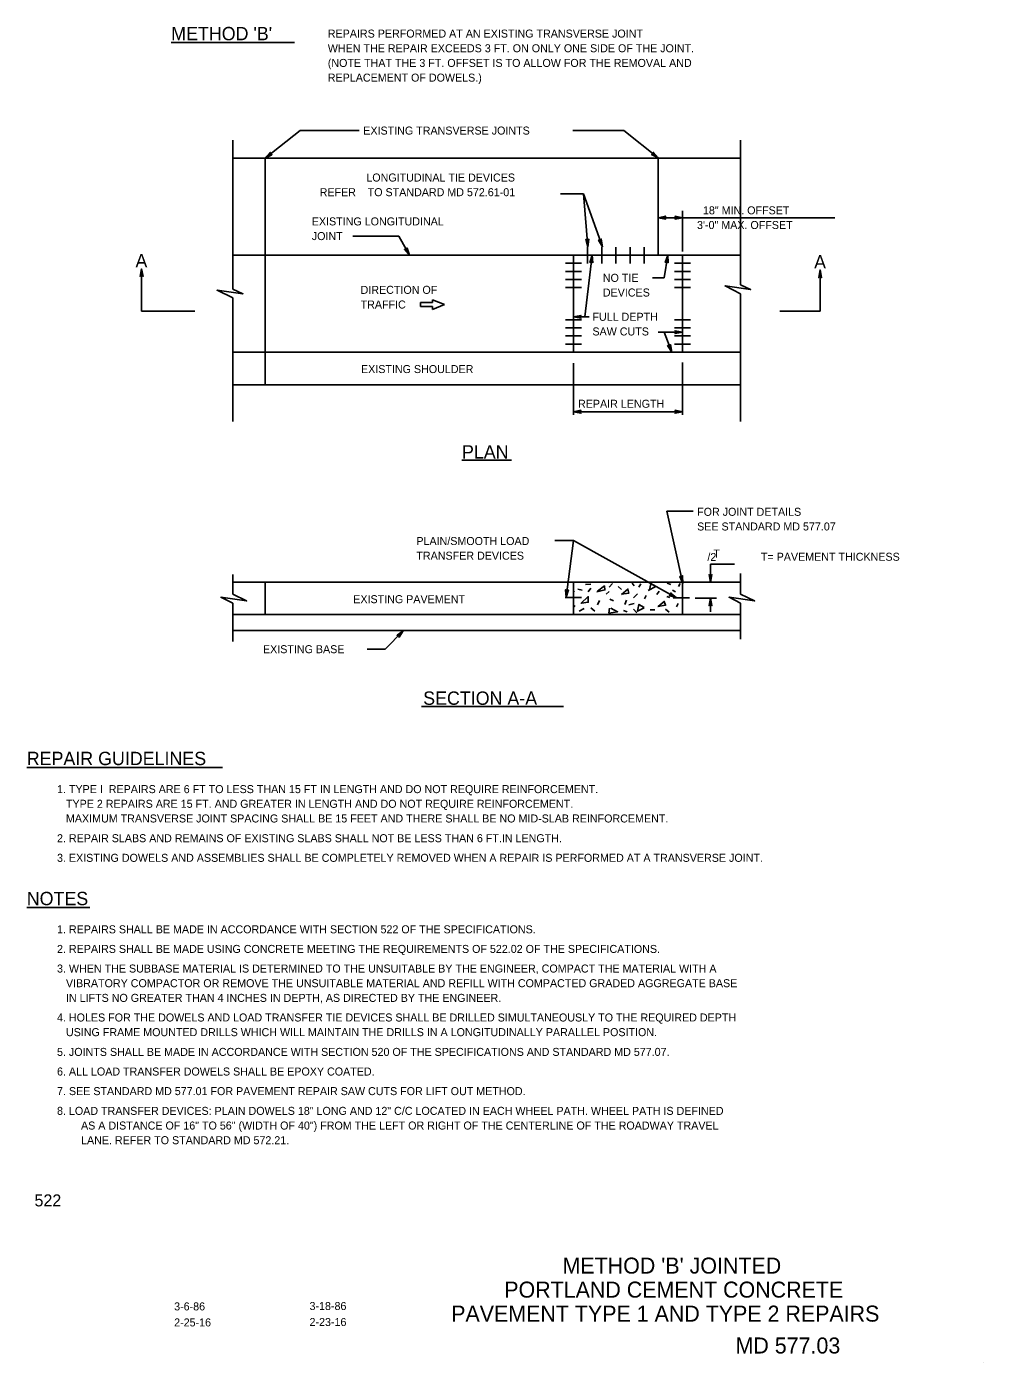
# Model space of a CAD drawing. Extents: x 1.1 to 8.2, y 0.2 to 10.2.
import ezdxf

# ---------------------------------------------------------------- set-up
doc = ezdxf.new("R2010")
doc.units = 0
for name, color, linetype in [('DETL-DIMS', 7, 'Continuous'), ('DETL-LINE', 7, 'Continuous'), ('DETL-NOTE', 7, 'Continuous'), ('DETL-PATT', 7, 'Continuous'), ('DETL-TITL', 7, 'Continuous'), ('TTLB-TEXT', 7, 'Continuous')]:
    doc.layers.add(name, color=color, linetype=linetype)

msp = doc.modelspace()

# ---------------------------------------------------------------- linework, layer by layer
at = {"layer": 'DETL-DIMS'}
for p, q in [((3.102, 9.42), (2.84, 9.212)), ((3.102, 9.42), (3.544, 9.42)), ((5.146, 9.42), (5.529, 9.42)), ((5.529, 9.42), (5.788, 9.215)), ((5.228, 8.945), (5.054, 8.945)), ((5.26, 8.549), (5.228, 8.945)), ((5.228, 8.945), (5.369, 8.549)), ((5.97, 8.513), (5.97, 8.819)), ((5.97, 8.767), (5.788, 8.767)), ((5.97, 8.767), (7.111, 8.767)), ((3.498, 8.629), (3.842, 8.629)), ((3.842, 8.629), (3.922, 8.485)), ((5.292, 8.486), (5.236, 8.024)), ((5.859, 8.486), (5.833, 8.316)), ((1.914, 8.066), (1.914, 8.383)), ((5.833, 8.316), (5.745, 8.316)), ((7.001, 8.066), (7.001, 8.375)), ((4.004, 8.1), (4.004, 8.132)), ((4.004, 8.132), (4.095, 8.132)), ((4.095, 8.132), (4.095, 8.152)), ((4.095, 8.152), (4.186, 8.116)), ((4.186, 8.116), (4.095, 8.079)), ((1.914, 8.066), (2.313, 8.066)), ((4.095, 8.1), (4.004, 8.1)), ((4.095, 8.079), (4.095, 8.1)), ((5.151, 8.024), (5.27, 8.024)), ((6.7, 8.066), (7.001, 8.066)), ((5.97, 7.908), (5.786, 7.908)), ((5.831, 7.908), (5.888, 7.759)), ((5.151, 7.29), (5.151, 7.676)), ((5.97, 7.29), (5.97, 7.681)), ((5.151, 7.312), (5.97, 7.312)), ((5.972, 6.025), (5.851, 6.567)), ((5.851, 6.567), (6.049, 6.567)), ((5.151, 6.347), (5.012, 6.347)), ((5.096, 5.921), (5.151, 6.347)), ((5.925, 5.917), (5.151, 6.347)), ((6.18, 6.169), (6.358, 6.169)), ((6.18, 6.035), (6.18, 6.169)), ((6.064, 5.915), (6.224, 5.915)), ((6.18, 5.813), (6.18, 5.915)), ((3.876, 5.67), (3.739, 5.532)), ((3.739, 5.532), (3.606, 5.532))]:
    msp.add_line(p, q, dxfattribs=at)
for points in [[(2.84, 9.212), (2.891, 9.239), (2.886, 9.239), (2.881, 9.24), (2.879, 9.243), (2.877, 9.246), (2.876, 9.251), (2.878, 9.256), (2.84, 9.212), (2.876, 9.251), (2.877, 9.246), (2.84, 9.212), (2.879, 9.243), (2.881, 9.24), (2.84, 9.212), (2.886, 9.239)], [(5.788, 9.215), (5.737, 9.241), (5.742, 9.241), (5.747, 9.243), (5.749, 9.245), (5.751, 9.249), (5.752, 9.253), (5.75, 9.258), (5.788, 9.215), (5.752, 9.253), (5.751, 9.249), (5.788, 9.215), (5.749, 9.245), (5.747, 9.243), (5.788, 9.215), (5.742, 9.241)], [(5.788, 8.767), (5.844, 8.778), (5.84, 8.775), (5.838, 8.771), (5.837, 8.767), (5.838, 8.763), (5.84, 8.76), (5.844, 8.756), (5.788, 8.767), (5.84, 8.76), (5.838, 8.763), (5.788, 8.767), (5.837, 8.767), (5.838, 8.771), (5.788, 8.767), (5.84, 8.775)], [(5.788, 8.767), (5.844, 8.778), (5.84, 8.775), (5.838, 8.771), (5.837, 8.767), (5.838, 8.763), (5.84, 8.76), (5.844, 8.756), (5.788, 8.767), (5.84, 8.76), (5.838, 8.763), (5.788, 8.767), (5.837, 8.767), (5.838, 8.771), (5.788, 8.767), (5.84, 8.775)], [(5.97, 8.767), (5.913, 8.756), (5.917, 8.76), (5.92, 8.763), (5.92, 8.767), (5.92, 8.771), (5.917, 8.775), (5.913, 8.778), (5.97, 8.767), (5.917, 8.775), (5.92, 8.771), (5.97, 8.767), (5.92, 8.767), (5.92, 8.763), (5.97, 8.767), (5.917, 8.76)], [(3.922, 8.485), (3.885, 8.529), (3.89, 8.527), (3.895, 8.527), (3.898, 8.528), (3.901, 8.53), (3.903, 8.534), (3.904, 8.539), (3.922, 8.485), (3.903, 8.534), (3.901, 8.53), (3.922, 8.485), (3.898, 8.528), (3.895, 8.527), (3.922, 8.485), (3.89, 8.527)], [(5.26, 8.549), (5.245, 8.605), (5.248, 8.6), (5.252, 8.598), (5.256, 8.598), (5.259, 8.599), (5.263, 8.602), (5.266, 8.606), (5.26, 8.549), (5.263, 8.602), (5.259, 8.599), (5.26, 8.549), (5.256, 8.598), (5.252, 8.598), (5.26, 8.549), (5.248, 8.6)], [(5.369, 8.549), (5.34, 8.599), (5.344, 8.596), (5.349, 8.595), (5.353, 8.595), (5.356, 8.597), (5.359, 8.601), (5.36, 8.606), (5.369, 8.549), (5.359, 8.601), (5.356, 8.597), (5.369, 8.549), (5.353, 8.595), (5.349, 8.595), (5.369, 8.549), (5.344, 8.596)], [(5.292, 8.486), (5.296, 8.429), (5.293, 8.434), (5.29, 8.436), (5.286, 8.438), (5.282, 8.437), (5.278, 8.436), (5.275, 8.432), (5.292, 8.486), (5.278, 8.436), (5.282, 8.437), (5.292, 8.486), (5.286, 8.438), (5.29, 8.436), (5.292, 8.486), (5.293, 8.434)], [(5.859, 8.486), (5.861, 8.429), (5.858, 8.434), (5.855, 8.437), (5.851, 8.438), (5.847, 8.438), (5.843, 8.436), (5.84, 8.432), (5.859, 8.486), (5.843, 8.436), (5.847, 8.438), (5.859, 8.486), (5.851, 8.438), (5.855, 8.437), (5.859, 8.486), (5.858, 8.434)], [(1.914, 8.383), (1.925, 8.327), (1.922, 8.331), (1.918, 8.333), (1.914, 8.334), (1.91, 8.333), (1.906, 8.331), (1.903, 8.327), (1.914, 8.383), (1.906, 8.331), (1.91, 8.333), (1.914, 8.383), (1.914, 8.334), (1.918, 8.333), (1.914, 8.383), (1.922, 8.331)], [(1.914, 8.383), (1.925, 8.327), (1.922, 8.331), (1.918, 8.333), (1.914, 8.334), (1.91, 8.333), (1.906, 8.331), (1.903, 8.327), (1.914, 8.383), (1.906, 8.331), (1.91, 8.333), (1.914, 8.383), (1.914, 8.334), (1.918, 8.333), (1.914, 8.383), (1.922, 8.331)], [(1.914, 8.383), (1.925, 8.327), (1.922, 8.331), (1.918, 8.333), (1.914, 8.334), (1.91, 8.333), (1.906, 8.331), (1.903, 8.327), (1.914, 8.383), (1.906, 8.331), (1.91, 8.333), (1.914, 8.383), (1.914, 8.334), (1.918, 8.333), (1.914, 8.383), (1.922, 8.331)], [(1.914, 8.383), (1.925, 8.327), (1.922, 8.331), (1.918, 8.333), (1.914, 8.334), (1.91, 8.333), (1.906, 8.331), (1.903, 8.327), (1.914, 8.383), (1.906, 8.331), (1.91, 8.333), (1.914, 8.383), (1.914, 8.334), (1.918, 8.333), (1.914, 8.383), (1.922, 8.331)], [(7.001, 8.375), (7.012, 8.318), (7.009, 8.323), (7.005, 8.325), (7.001, 8.326), (6.997, 8.325), (6.994, 8.323), (6.991, 8.318), (7.001, 8.375), (6.994, 8.323), (6.997, 8.325), (7.001, 8.375), (7.001, 8.326), (7.005, 8.325), (7.001, 8.375), (7.009, 8.323)], [(5.151, 8.024), (5.208, 8.034), (5.204, 8.031), (5.201, 8.028), (5.201, 8.024), (5.201, 8.02), (5.204, 8.016), (5.208, 8.013), (5.151, 8.024), (5.204, 8.016), (5.201, 8.02), (5.151, 8.024), (5.201, 8.024), (5.201, 8.028), (5.151, 8.024), (5.204, 8.031)], [(5.97, 7.908), (5.913, 7.898), (5.917, 7.901), (5.92, 7.904), (5.92, 7.908), (5.92, 7.912), (5.917, 7.916), (5.913, 7.919), (5.97, 7.908), (5.917, 7.916), (5.92, 7.912), (5.97, 7.908), (5.92, 7.908), (5.92, 7.904), (5.97, 7.908), (5.917, 7.901)], [(5.97, 7.908), (5.913, 7.898), (5.917, 7.901), (5.92, 7.904), (5.92, 7.908), (5.92, 7.912), (5.917, 7.916), (5.913, 7.919), (5.97, 7.908), (5.917, 7.916), (5.92, 7.912), (5.97, 7.908), (5.92, 7.908), (5.92, 7.904), (5.97, 7.908), (5.917, 7.901)], [(5.888, 7.759), (5.858, 7.808), (5.862, 7.805), (5.866, 7.804), (5.87, 7.805), (5.873, 7.807), (5.876, 7.81), (5.878, 7.815), (5.888, 7.759), (5.876, 7.81), (5.873, 7.807), (5.888, 7.759), (5.87, 7.805), (5.866, 7.804), (5.888, 7.759), (5.862, 7.805)], [(5.151, 7.312), (5.208, 7.323), (5.204, 7.32), (5.201, 7.316), (5.201, 7.312), (5.201, 7.308), (5.204, 7.304), (5.208, 7.301), (5.151, 7.312), (5.204, 7.304), (5.201, 7.308), (5.151, 7.312), (5.201, 7.312), (5.201, 7.316), (5.151, 7.312), (5.204, 7.32)], [(5.151, 7.312), (5.208, 7.323), (5.204, 7.32), (5.201, 7.316), (5.201, 7.312), (5.201, 7.308), (5.204, 7.304), (5.208, 7.301), (5.151, 7.312), (5.204, 7.304), (5.201, 7.308), (5.151, 7.312), (5.201, 7.312), (5.201, 7.316), (5.151, 7.312), (5.204, 7.32)], [(5.97, 7.312), (5.913, 7.301), (5.917, 7.304), (5.92, 7.308), (5.92, 7.312), (5.92, 7.316), (5.917, 7.32), (5.913, 7.323), (5.97, 7.312), (5.917, 7.32), (5.92, 7.316), (5.97, 7.312), (5.92, 7.312), (5.92, 7.308), (5.97, 7.312), (5.917, 7.304)], [(5.972, 6.025), (5.95, 6.078), (5.954, 6.074), (5.958, 6.073), (5.962, 6.073), (5.965, 6.075), (5.968, 6.078), (5.97, 6.083), (5.972, 6.025), (5.968, 6.078), (5.965, 6.075), (5.972, 6.025), (5.962, 6.073), (5.958, 6.073), (5.972, 6.025), (5.954, 6.074)], [(6.18, 6.035), (6.169, 6.091), (6.172, 6.087), (6.176, 6.085), (6.18, 6.084), (6.183, 6.085), (6.187, 6.087), (6.19, 6.091), (6.18, 6.035), (6.187, 6.087), (6.183, 6.085), (6.18, 6.035), (6.18, 6.084), (6.176, 6.085), (6.18, 6.035), (6.172, 6.087)], [(5.096, 5.921), (5.093, 5.978), (5.095, 5.974), (5.099, 5.971), (5.102, 5.97), (5.106, 5.97), (5.11, 5.972), (5.114, 5.976), (5.096, 5.921), (5.11, 5.972), (5.106, 5.97), (5.096, 5.921), (5.102, 5.97), (5.099, 5.971), (5.096, 5.921), (5.095, 5.974)], [(5.925, 5.917), (5.871, 5.935), (5.876, 5.936), (5.88, 5.938), (5.882, 5.941), (5.884, 5.944), (5.884, 5.949), (5.881, 5.954), (5.925, 5.917), (5.884, 5.949), (5.884, 5.944), (5.925, 5.917), (5.882, 5.941), (5.88, 5.938), (5.925, 5.917), (5.876, 5.936)], [(6.18, 5.915), (6.19, 5.859), (6.187, 5.863), (6.183, 5.866), (6.18, 5.866), (6.176, 5.866), (6.172, 5.863), (6.169, 5.859), (6.18, 5.915), (6.172, 5.863), (6.176, 5.866), (6.18, 5.915), (6.18, 5.866), (6.183, 5.866), (6.18, 5.915), (6.187, 5.863)], [(3.876, 5.67), (3.844, 5.622), (3.845, 5.627), (3.844, 5.632), (3.842, 5.635), (3.838, 5.637), (3.834, 5.638), (3.829, 5.637), (3.876, 5.67), (3.834, 5.638), (3.838, 5.637), (3.876, 5.67), (3.842, 5.635), (3.844, 5.632), (3.876, 5.67), (3.845, 5.627)]]:
    msp.add_lwpolyline(points, dxfattribs=at)
at = {"layer": 'DETL-LINE'}
for p, q in [((2.598, 9.349), (2.598, 8.232)), ((6.405, 9.349), (6.405, 8.264)), ((2.598, 9.212), (6.405, 9.212)), ((2.84, 9.212), (2.84, 7.515)), ((5.788, 8.485), (5.788, 9.212)), ((5.257, 8.424), (5.257, 8.546)), ((5.364, 8.424), (5.364, 8.546)), ((5.47, 8.424), (5.47, 8.546)), ((5.576, 8.424), (5.576, 8.546)), ((5.682, 8.424), (5.682, 8.546)), ((2.598, 8.485), (6.405, 8.485)), ((5.091, 8.425), (5.212, 8.425)), ((5.151, 7.758), (5.151, 8.486)), ((6.03, 8.425), (5.909, 8.425)), ((5.97, 7.758), (5.97, 8.486)), ((5.97, 7.758), (5.97, 8.486)), ((5.091, 8.364), (5.212, 8.364)), ((6.03, 8.364), (5.909, 8.364)), ((5.091, 8.304), (5.212, 8.304)), ((5.091, 8.243), (5.212, 8.243)), ((6.03, 8.304), (5.909, 8.304)), ((6.03, 8.243), (5.909, 8.243)), ((2.598, 8.166), (2.598, 7.239)), ((6.405, 8.197), (6.405, 7.239)), ((5.091, 8.001), (5.212, 8.001)), ((5.091, 7.94), (5.212, 7.94)), ((6.03, 8.001), (5.909, 8.001)), ((6.03, 7.94), (5.909, 7.94)), ((5.091, 7.88), (5.212, 7.88)), ((5.091, 7.819), (5.212, 7.819)), ((6.03, 7.88), (5.909, 7.88)), ((6.03, 7.819), (5.909, 7.819)), ((2.598, 7.758), (6.405, 7.758)), ((2.598, 7.515), (6.405, 7.515)), ((2.598, 6.093), (2.598, 5.944)), ((2.598, 6.035), (6.405, 6.035)), ((2.84, 6.035), (2.84, 5.793)), ((5.151, 6.035), (5.151, 5.793)), ((5.97, 6.035), (5.97, 5.793)), ((6.405, 6.099), (6.405, 5.945)), ((5.151, 5.919), (5.09, 5.919)), ((5.151, 5.919), (5.212, 5.919)), ((5.899, 5.917), (6.021, 5.917)), ((2.598, 5.877), (2.598, 5.589)), ((6.405, 5.878), (6.405, 5.606)), ((2.598, 5.793), (6.405, 5.793)), ((2.598, 5.671), (6.405, 5.671))]:
    msp.add_line(p, q, dxfattribs=at)
for points in [[(2.598, 8.166), (2.48, 8.223), (2.673, 8.197), (2.598, 8.232)], [(6.405, 8.197), (6.288, 8.255), (6.48, 8.228), (6.405, 8.264)], [(2.598, 5.877), (2.509, 5.921), (2.701, 5.894), (2.598, 5.944)], [(6.405, 5.878), (6.318, 5.921), (6.51, 5.894), (6.405, 5.945)]]:
    msp.add_lwpolyline(points, dxfattribs=at)
at = {"layer": 'DETL-NOTE'}
for p, q in [((2.136, 10.08), (3.06, 10.08)), ((1.053, 4.646), (2.521, 4.646)), ((1.053, 3.596), (1.527, 3.596))]:
    msp.add_line(p, q, dxfattribs=at)
at = {"layer": 'DETL-PATT'}
for p, q in [((5.242, 6.016), (5.281, 6.019)), ((5.419, 5.996), (5.445, 6.025)), ((5.592, 6.028), (5.608, 6.006)), ((5.627, 6.035), (5.627, 6.035)), ((5.656, 6.022), (5.643, 5.996)), ((5.855, 6.028), (5.881, 6.016)), ((5.939, 6.003), (5.952, 6.025)), ((5.159, 5.967), (5.156, 5.964)), ((5.185, 5.983), (5.217, 5.974)), ((5.262, 5.961), (5.281, 5.99)), ((5.396, 5.945), (5.419, 5.964)), ((5.486, 6.003), (5.512, 5.98)), ((5.631, 5.948), (5.602, 5.916)), ((5.698, 5.935), (5.685, 5.91)), ((5.778, 5.942), (5.794, 5.967)), ((5.852, 5.926), (5.875, 5.919)), ((5.894, 5.974), (5.916, 5.961)), ((5.156, 5.858), (5.165, 5.852)), ((5.233, 5.836), (5.194, 5.817)), ((5.281, 5.842), (5.313, 5.817)), ((5.332, 5.865), (5.348, 5.897)), ((5.425, 5.906), (5.451, 5.894)), ((5.528, 5.823), (5.554, 5.813)), ((5.55, 5.9), (5.538, 5.868)), ((5.608, 5.874), (5.566, 5.865)), ((5.602, 5.833), (5.627, 5.804)), ((5.727, 5.826), (5.762, 5.826)), ((5.842, 5.833), (5.868, 5.81)), ((5.923, 5.849), (5.936, 5.874))]:
    msp.add_line(p, q, dxfattribs=at)
for points in [[(5.416, 6.035), (5.416, 6.032), (5.435, 6.035)], [(5.711, 5.971), (5.769, 6.003), (5.733, 6.022), (5.721, 5.977)], [(5.213, 5.878), (5.262, 5.884), (5.262, 5.926), (5.207, 5.874)], [(5.326, 5.961), (5.387, 5.977), (5.384, 6.006), (5.332, 5.967)], [(5.512, 5.945), (5.566, 5.951), (5.56, 5.983), (5.512, 5.942)], [(5.422, 5.839), (5.416, 5.801)], [(5.416, 5.801), (5.483, 5.813), (5.432, 5.839)], [(5.682, 5.842), (5.631, 5.817), (5.643, 5.868), (5.682, 5.845)], [(5.785, 5.852), (5.842, 5.862), (5.833, 5.89), (5.788, 5.852)]]:
    msp.add_lwpolyline(points, dxfattribs=at)
at = {"layer": 'DETL-TITL'}
for p, q in [((4.316, 6.949), (4.686, 6.949)), ((4.012, 5.102), (5.077, 5.102))]:
    msp.add_line(p, q, dxfattribs=at)
at = {"layer": 'TTLB-TEXT'}
msp.add_line((8.224, 0.186), (8.224, 0.186), dxfattribs=at)

# ---------------------------------------------------------------- texts
at = {"layer": 'DETL-NOTE'}
for s, height, p in [("METHOD 'B'", 0.1, (2.136, 10.097)), ('REPAIRS PERFORMED AT AN EXISTING TRANSVERSE JOINT', 0.06, (3.31, 10.117)), ('WHEN THE REPAIR EXCEEDS 3 FT. ON ONLY ONE SIDE OF THE JOINT.', 0.06, (3.31, 10.007)), ('(NOTE THAT THE 3 FT. OFFSET IS TO ALLOW FOR THE REMOVAL AND', 0.06, (3.31, 9.897)), ('REPLACEMENT OF DOWELS.)', 0.06, (3.31, 9.787)), ('EXISTING TRANSVERSE JOINTS', 0.06, (3.576, 9.39)), ('LONGITUDINAL TIE DEVICES', 0.06, (3.599, 9.038)), ('REFER ', 0.06, (3.249, 8.928)), ('TO STANDARD MD 572.61-01', 0.06, (3.609, 8.928)), ('  18" MIN. OFFSET', 0.06, (6.078, 8.792)), ('EXISTING LONGITUDINAL', 0.06, (3.19, 8.709)), ('3\'-0" MAX. OFFSET', 0.06, (6.078, 8.682)), ('JOINT ', 0.06, (3.19, 8.599)), ('A', 0.1, (1.868, 8.394)), ('A', 0.1, (6.956, 8.386)), ('NO TIE', 0.06, (5.372, 8.286)), ('DIRECTION OF', 0.06, (3.556, 8.196)), ('DEVICES', 0.06, (5.372, 8.176)), ('TRAFFIC', 0.06, (3.556, 8.086)), ('FULL DEPTH', 0.06, (5.294, 7.994)), ('SAW CUTS', 0.06, (5.294, 7.884)), ('EXISTING SHOULDER', 0.06, (3.559, 7.602)), ('REPAIR LENGTH', 0.06, (5.186, 7.342)), ('FOR JOINT DETAILS', 0.06, (6.079, 6.532)), ('SEE STANDARD MD 577.07', 0.06, (6.079, 6.422)), ('PLAIN/SMOOTH LOAD ', 0.06, (3.974, 6.313)), ('TRANSFER DEVICES', 0.06, (3.974, 6.203)), ('  /2', 0.06, (6.111, 6.193)), ('T', 0.06, (6.2, 6.219)), ('T= PAVEMENT THICKNESS', 0.06, (6.557, 6.195)), ('EXISTING PAVEMENT', 0.06, (3.501, 5.877)), ('EXISTING BASE', 0.06, (2.824, 5.502)), ('REPAIR GUIDELINES', 0.1, (1.053, 4.663)), ('1. TYPE I  REPAIRS ARE 6 FT TO LESS THAN 15 FT IN LENGTH AND DO NOT REQUIRE REINFORCEMENT. ', 0.06, (1.28, 4.453)), ('   TYPE 2 REPAIRS ARE 15 FT. AND GREATER IN LENGTH AND DO NOT REQUIRE REINFORCEMENT. ', 0.06, (1.28, 4.343)), ('   MAXIMUM TRANSVERSE JOINT SPACING SHALL BE 15 FEET AND THERE SHALL BE NO MID-SLAB REINFORCEMENT.', 0.06, (1.28, 4.233)), ('2. REPAIR SLABS AND REMAINS OF EXISTING SLABS SHALL NOT BE LESS THAN 6 FT.IN LENGTH.', 0.06, (1.28, 4.085)), ('3. EXISTING DOWELS AND ASSEMBLIES SHALL BE COMPLETELY REMOVED WHEN A REPAIR IS PERFORMED AT A TRANSVERSE JOINT.', 0.06, (1.28, 3.938)), ('NOTES', 0.1, (1.053, 3.613)), ('1. REPAIRS SHALL BE MADE IN ACCORDANCE WITH SECTION 522 OF THE SPECIFICATIONS.', 0.06, (1.28, 3.402)), ('2. REPAIRS SHALL BE MADE USING CONCRETE MEETING THE REQUIREMENTS OF 522.02 OF THE SPECIFICATIONS.', 0.06, (1.28, 3.255)), ('3. WHEN THE SUBBASE MATERIAL IS DETERMINED TO THE UNSUITABLE BY THE ENGINEER, COMPACT THE MATERIAL WITH A ', 0.06, (1.28, 3.108)), ('   VIBRATORY COMPACTOR OR REMOVE THE UNSUITABLE MATERIAL AND REFILL WITH COMPACTED GRADED AGGREGATE BASE ', 0.06, (1.28, 2.998)), ('   IN LIFTS NO GREATER THAN 4 INCHES IN DEPTH, AS DIRECTED BY THE ENGINEER.', 0.06, (1.28, 2.888)), ('4. HOLES FOR THE DOWELS AND LOAD TRANSFER TIE DEVICES SHALL BE DRILLED SIMULTANEOUSLY TO THE REQUIRED DEPTH', 0.06, (1.28, 2.741)), ('   USING FRAME MOUNTED DRILLS WHICH WILL MAINTAIN THE DRILLS IN A LONGITUDINALLY PARALLEL POSITION.', 0.06, (1.28, 2.631)), ('5. JOINTS SHALL BE MADE IN ACCORDANCE WITH SECTION 520 OF THE SPECIFICATIONS AND STANDARD MD 577.07.', 0.06, (1.28, 2.483)), ('6. ALL LOAD TRANSFER DOWELS SHALL BE EPOXY COATED.', 0.06, (1.28, 2.336)), ('7. SEE STANDARD MD 577.01 FOR PAVEMENT REPAIR SAW CUTS FOR LIFT OUT METHOD.', 0.06, (1.28, 2.189)), ('8. LOAD TRANSFER DEVICES: PLAIN DOWELS 18" LONG AND 12" C/C LOCATED IN EACH WHEEL PATH. WHEEL PATH IS DEFINED ', 0.06, (1.28, 2.041)), ('AS A DISTANCE OF 16" TO 56" (WIDTH OF 40") FROM THE LEFT OR RIGHT OF THE CENTERLINE OF THE ROADWAY TRAVEL ', 0.06, (1.46, 1.931)), ('LANE. REFER TO STANDARD MD 572.21.', 0.06, (1.46, 1.821))]:
    msp.add_text(s, height=height, dxfattribs=at).set_placement(p)
at = {"layer": 'DETL-TITL'}
for s, p in [('PLAN', (4.316, 6.961)), ('SECTION A-A', (4.025, 5.115))]:
    msp.add_text(s, height=0.1, dxfattribs=at).set_placement(p)
at = {"layer": 'TTLB-TEXT'}
for s, height, p in [('522', 0.09, (1.111, 1.355)), ("METHOD 'B' JOINTED", 0.12, (5.07, 0.851)), ('PORTLAND CEMENT CONCRETE', 0.12, (4.633, 0.671)), ('3-6-86', 0.06, (2.158, 0.575)), ('3-18-86', 0.06, (3.173, 0.578)), ('PAVEMENT TYPE 1 AND TYPE 2 REPAIRS', 0.12, (4.235, 0.491)), ('2-25-16', 0.06, (2.158, 0.455)), ('2-23-16', 0.06, (3.173, 0.458)), ('MD 577.03', 0.12, (6.367, 0.252))]:
    msp.add_text(s, height=height, dxfattribs=at).set_placement(p)

doc.saveas('drawing.dxf')
